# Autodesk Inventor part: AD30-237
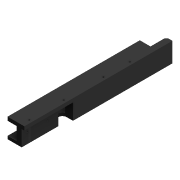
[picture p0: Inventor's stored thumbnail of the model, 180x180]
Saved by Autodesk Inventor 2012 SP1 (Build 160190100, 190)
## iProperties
Shininess: 0.0
Created: 2000-06
Part Number: AD30-237
Project: BONDING PRESS
Description: VACUUM PLATE GUIDE L/R
Document SubType Name: Modeling
Designer: Ron
Material: Delrin, White
Density: 1 g/cm^3
Density: 0.0
Volumn: 0.0
Area: 0.0
PropertySet Name: Model Information
Control State: 0
Master: False
Checked Out: False
Title: VACUUM PLATE GUIDE L/R
Author: Ron
Revision Number: 01
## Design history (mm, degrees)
node "Extrusion1" dims "d5" = 280, "d6" = 0
  sketch "Sketch1"
    geometry: L1 (2.687, 11.75)-(-14.493, 11.75); L2 (-14.493, 11.75)-(-14.493, 18.45); L3 (-14.493, 18.45)-(17.257, 18.45); L4 (17.257, 18.45)-(17.257, -18.45); L5 (17.257, -18.45)-(-14.493, -18.45); L6 (-14.493, -18.45)-(-14.493, -12.95); L7 (-14.493, -12.95)-(2.687, -12.95); L8 (2.687, -12.95)-(2.687, 11.75); 1 further point
    constraints: 16 end point, 5 parallel, 2 collinear, 1 horizontal, 1 perpendicular
    dimensions: "d0" = 24.7 distance of L7.end L1.start; "d4" = 31.75 distance of L4.end L5.end; "d50" = 14.57 distance between parallel lines of L4 L8; "d93" = 11.75 distance from line of L1 point (0, 0); "d94" = 18.45 distance from line of L3 point (0, 0); "d95" = 36.9 distance between parallel lines of L5 L3
node "Extrusion2" dims "d8" = 10, "d9" = 0
  sketch "Sketch2"
    geometry: L1 (31.75, 280)-(0, 280) reference; L2 (0, 280)-(17.18, 280); L3 (17.18, 280)-(17.18, 250); L4 (17.18, 250)-(0, 250); L5 (0, 250)-(0, 280); L6 (17.18, 0)-(17.18, 280) reference
    constraints: 8 end point, 2 parallel, 1 collinear, 1 horizontal, 1 perpendicular
    dimensions: "d7" = 30 distance between parallel lines of L4 L1
node "Chamfer1" dims "d10" = 6, "d11" = 6, "d90" = 45 deg
node "Chamfer2" dims "d12" = 3, "d13" = 3, "d91" = 45 deg
node "Chamfer3" dims "d14" = 3, "d15" = 3, "d92" = 45 deg
node "Hole1" dims "d21" = 3.242, "d22" = 4, "d23" = 2, "d24" = 60 deg, "d25" = 10, "d26" = 118 deg, "d87" = 6
  sketch "Sketch3"
    geometry: L1 (31.75, 0)-(0, 0) reference; L2 (31.75, 0)-(31.75, 280) reference; L3 (31.75, 280)-(23.18, 280) reference; L4 (20.18, 250)-(20.18, 277) reference; L5 (25.75, 15)-(25.75, 80); L6 (25.75, 80)-(25.75, 155); L7 (25.75, 155)-(25.75, 205)
    constraints: 6 end point, 3 parallel
    dimensions: "d16" = 15 distance from line of L5.start L1; "d17" = 6 distance between parallel lines of L2 L5; "d18" = 65 distance of L5.end L5.start; "d19" = 75 distance from line of L3 L7.end; "d20" = 50 distance of L6.end L7.end
node "Extrusion5" dims "d37" = 30, "d38" = 0
  sketch "Sketch6"
    geometry: L1 (0, 280)-(26.75, 280) reference; L2 (31.75, 165)-(31.75, 0) reference; L3 (31.75, 188)-(19.75, 188); L4 (11.75, 196)-(11.75, 203); L5 (19.75, 211)-(31.75, 211); L6 (0, 0)-(31.75, 0) reference; L7 (31.75, 188)-(31.75, 211); A1 r 8 centre (19.75, 196) between (11.75, 196) and (19.75, 188); A2 r 8 centre (19.75, 203) between (19.75, 211) and (11.75, 203); 1 further point
    constraints: 8 end point, 4 perpendicular, 4 point on circle, 4 tangent, 2 centre point, 1 collinear, 1 equal radius
    dimensions: "d34" = 77 distance from line of L1 A2.centre; "d35" = 7 distance of A1.centre A2.centre; "d36" = 8 radius of A1; "d40" = 20 distance between parallel lines of L2 L4
node "Extrusion6" dims "d41" = 5, "d42" = 0
  sketch "Sketch7"
    geometry: L1 (92, 30)-(0, 30); L2 (0, 30)-(0, 0); L3 (0, 0)-(92, 0); L4 (92, 0)-(92, 30)
    constraints: 8 end point, 2 parallel, 1 horizontal, 1 perpendicular
node "Hole2" dims "d44" = 2.459, "d45" = 4, "d46" = 2, "d47" = 60 deg, "d48" = 8, "d49" = 118 deg, "d88" = 6
  sketch "Sketch8"
    geometry: L1 (69, 0)-(0, 0) reference; L2 (8.252, 19.525)-(13.252, 19.525); A1 r 1.6 centre (8.252, 19.525) between (8.252, 21.125) and (8.252, 17.925) reference; A2 r 1.6 centre (13.252, 19.525) between (13.252, 17.925) and (13.252, 21.125) reference; 2 further points
    constraints: 2 end point, 1 horizontal alignment, 1 midpoint, 1 parallel
    dimensions: "d43" = 38.1 distance of point (48.852, 19.525) point (10.752, 19.525)
body "Solid1"
